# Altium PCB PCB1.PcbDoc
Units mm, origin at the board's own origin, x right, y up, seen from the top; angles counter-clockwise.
Board outline 14.8 x 18 mm, 2 copper layers (Top Layer, Bottom Layer); 2 components, 5 nets, 10 pads, 3 vias.
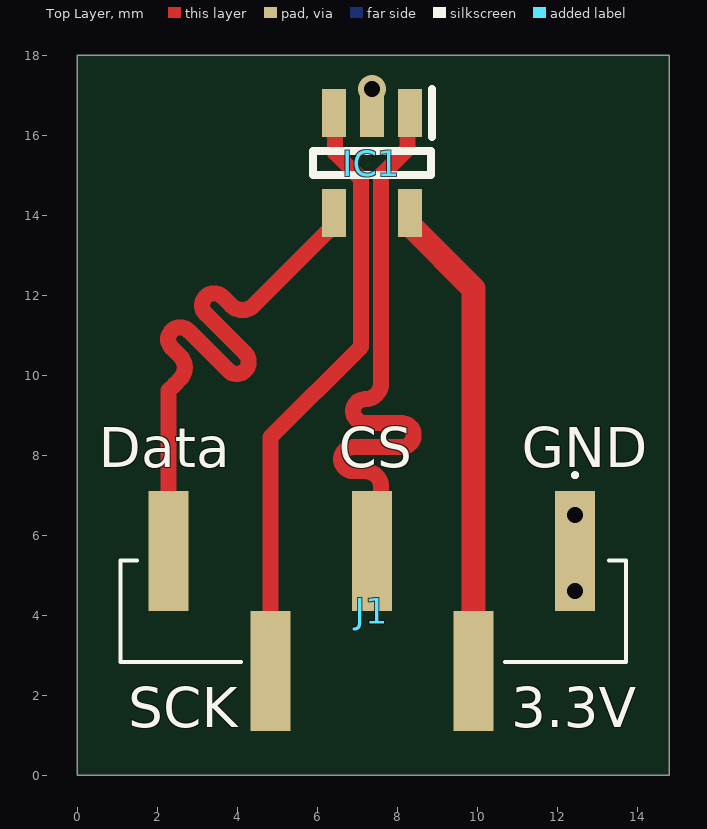
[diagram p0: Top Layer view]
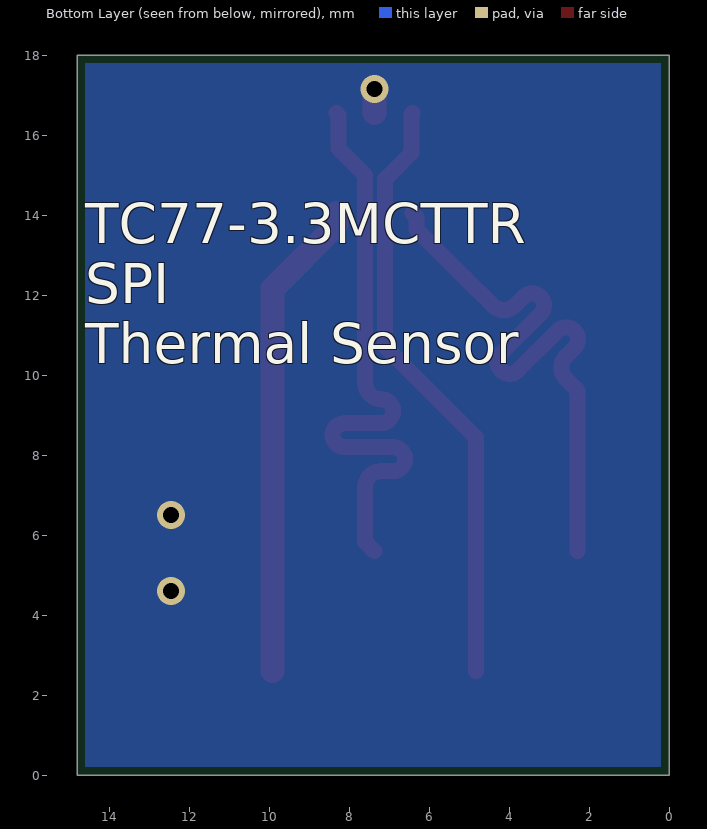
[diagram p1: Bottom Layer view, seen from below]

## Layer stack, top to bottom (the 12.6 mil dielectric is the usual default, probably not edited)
Top Solder: solder mask 0.0102, Solder Resist, Dk 3.5
Top Layer: signal copper 0.0356
Dielectric 1: dielectric 0.32, FR-4, Dk 4.8
Bottom Layer: signal copper 0.0356
Bottom Solder: solder mask 0.0102, Solder Resist, Dk 3.5

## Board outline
0,0 0,18 14.8,18 14.8,0

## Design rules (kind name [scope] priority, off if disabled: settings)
BoardOutlineClearance [All] p1: gap=0.2 ignorepadtopadclearanceinfootprint=FALSE
Clearance [All] p1: gap=0.102 ignorepadtopadclearanceinfootprint=FALSE except(0.127: Arc-Via Track-Via SMDPad-Via THPad-Via Via-Via Via-Fill Via-Poly Via-Region Via-Text; 0.25: Arc-Hole Track-Hole SMDPad-Hole THPad-Hole Via-Hole Fill-Hole Poly-Hole Region-Hole Text-Hole)
ComponentClearance [All] p1: gap=0.102 collisioncheckmode=3 verticalgap=0.102 showdistances=TRUE
DiffPairsRouting [All] p1: maxlimit=0.102 minlimit=0.102 mostfreqgap=0.102 toplayer_minwidth=0.102 toplayer_maxwidth=1816.048 toplayer_prefwidth=0.102 bottomlayer_minwidth=0.102 bottomlayer_maxwidth=1816.048 bottomlayer_prefwidth=0.102 maxuncoupledlength=12.7
Height [All] p1: minheight=0 maxheight=1816.048 prefheight=12.7
HoleSize [All] p1: absolutevalues=TRUE maxlimit=6.3 minlimit=0.2 maxpercent=80.000 minpercent=20.000
HoleToHoleClearance [All] p1: gap=0.25 allowstackedmicrovias=FALSE
MinimumAnnularRing [All] p1: minimumring=0.076
MinimumSolderMaskSliver [All] p1: minsoldermaskwidth=0
PlaneClearance [All] p1: clearance=0.102
PlaneConnect PlaneConnectPowerPads [InPadClass('PowerPads')] p1: planeconnectstyle=Direct reliefexpansion=0.508 reliefentries=4 reliefconductorwidth=0.254 reliefairgap=0.254
PlaneConnect [All] p2: pad.planeconnectstyle=Relief pad.reliefexpansion=0.3 pad.reliefentries=4 pad.reliefconductorwidth=0.102 pad.reliefairgap=0.102 via.planeconnectstyle=Direct via.reliefexpansion=0.3 via.reliefentries=4 via.reliefconductorwidth=0.127 via.reliefairgap=0.127
PolygonConnect PolygonConnectPowerPads [All vs (InPadClass('PowerPads'))] p1: connectstyle=Direct reliefconductorwidth=0.254 reliefentries=4 polygonreliefangle="90 Angle" airgapwidth=0.254
PolygonConnect [All] p2: thpad.connectstyle=Relief thpad.reliefconductorwidth=0.102 thpad.reliefentries=4 thpad.polygonreliefangle="90 Angle" thpad.airgapwidth=0.102 smdpad.connectstyle=Relief smdpad.reliefconductorwidth=0.102 smdpad.reliefentries=4 smdpad.polygonreliefangle="90 Angle" smdpad.airgapwidth=0.102 via.connectstyle=Direct via.reliefconductorwidth=0.127 via.reliefentries=4 via.polygonreliefangle="90 Angle" via.airgapwidth=0.127
RoomDefinition Sheet1 [InComponentClass('Sheet1')] p1: confinementstyle=ConfineIn formatcopy=TRUE lockcomponents=FALSE outline 0,0 14.8,0 14.8,18 0,18
RoutingVias [All] p1: holewidth=0.2 width=0.45 viastyle="Through Hole" minholewidth=0.2 minwidth=0.45 maxholewidth=6.3 maxwidth=6.55
SilkToSilkClearance [All] p1: silktosilkclearance=0
SilkToSolderMaskClearance [IsPad] p1: minsilkscreentomaskgap=0.102 clearancetoexposedcopper=TRUE
SolderMaskExpansion [All] p1: expansion=0.075 istentingtop=FALSE
Width [All] p1: maxlimit=2 minlimit=0.1 preferedwidth=0.2
20 further rules are at their usual default settings.

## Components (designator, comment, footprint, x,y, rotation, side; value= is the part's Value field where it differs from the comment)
IC1 "TC77-3.3MCTTR" SOT95P280X145-5N 7.37,15.3 r270 top
J1 "61000618221_5pins" 61000618221_5pins 6.1,4.1 r180 top

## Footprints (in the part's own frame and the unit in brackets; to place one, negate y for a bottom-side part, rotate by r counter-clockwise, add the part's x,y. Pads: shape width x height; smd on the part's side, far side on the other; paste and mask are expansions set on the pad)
61000618221_5pins [mm]
  rect 1x3 smd: 1(-6.35,-1.5) 2(-3.81,1.5) 3(-1.27,-1.5) 4(1.27,1.5) 5(3.81,-1.5)
  silkscreen extent -7.62,-3.45 5.02,1.27
SOT95P280X145-5N [mm]
  rect 1.2x0.6 smd: 1(-1.25,0.95) 2(-1.25,0) 3(-1.25,-0.95) 4(1.25,-0.95) 5(1.25,0.95)
  silkscreen extent -1.85,-1.48 0.3,1.5, body extent -1.4,-1.48 1.4,1.48, height 1.45

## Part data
IC1: "Integrated Circuit", Manufacturer_Name=Microchip, Mouser Part Number=579-TC77-3.3MCTTR
J1: "Connector", Manufacturer_Name="Wurth Elektronik", Manufacturer_Part_Number=61000618221, Mouser Part Number=710-61000618221

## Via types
v1: diameter 0.7, hole 0.4, Top Layer to Bottom Layer, 3 vias

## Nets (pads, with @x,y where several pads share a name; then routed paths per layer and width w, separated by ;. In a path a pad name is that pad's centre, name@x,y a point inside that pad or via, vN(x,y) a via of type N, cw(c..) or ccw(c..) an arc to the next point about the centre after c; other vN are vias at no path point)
CS: IC1.1 J1.3 | length 15.3
  Top Layer w0.4: J1.3 7.6,5.83 7.6,7 7.6,7.2 ccw(c7.2,7.2) 7.2,7.6 6.9,7.6 cw(c6.9,7.9) 6.9,8.2 8.116,8.2 ccw(c8.116,8.5) 8.116,8.8 7.2,8.8 cw(c7.2,9.1) 7.2,9.4 ccw(c7.2,9.8) 7.6,9.8 7.6,10.415 7.6,15 8.261,15.661 8.261,16.491 IC1.1
GND: IC1.2 J1.1 | length 0.6
  Top Layer w0.6: IC1.2 v1(7.37,17.15)
  other v1: 12.45,4.6 12.45,6.5
IN/OUT: IC1.4 J1.5 | length 15
  Top Layer w0.4: J1.5 2.29,9.62 2.435,9.765 2.576,9.906 ccw(c2.294,10.189) 2.576,10.472 2.364,10.684 cw(c2.576,10.896) 2.364,11.109 cw(c2.576,10.896) 2.789,11.109 3.779,10.119 ccw(c3.991,10.331) 4.203,10.119 ccw(c3.991,10.331) 4.203,10.543 3.213,11.533 cw(c3.425,11.745) 3.213,11.957 cw(c3.425,11.745) 3.637,11.957 3.849,11.745 ccw(c4.132,12.028) 4.415,11.745 5.092,12.422 6.32,13.65 6.32,13.95 IC1.4
SCK: IC1.3 J1.4 | length 15.2
  Top Layer w0.4: J1.4 4.83,8.443 7.098,10.712 7.098,14.902 6.447,15.553 6.447,16.523 IC1.3
VDD: IC1.5 J1.2 | length 12.1
  Top Layer w0.6: IC1.5 8.32,13.75 9.91,12.16 J1.2

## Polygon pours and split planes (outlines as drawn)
GND on Bottom Layer "NONET_L01_P-001" (solid, pour order 0): 0,18 0,0 14.8,0 14.8,18

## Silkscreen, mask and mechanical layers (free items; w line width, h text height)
Top Overlay:
  text "Data" at 0.541,7.7 h1
  text "CS" at 6.537,7.7 h1
  text "GND" at 11.117,7.7 h1
  text "SCK" at 1.284,1.2 h1
  text "3.3V" at 10.851,1.2 h1
Bottom Overlay:
  text "TC77-3.3MCTTR / SPI  / Thermal Sensor" at 14.6,10.291 h1
Mechanical 1:
  the board outline again, w0.2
